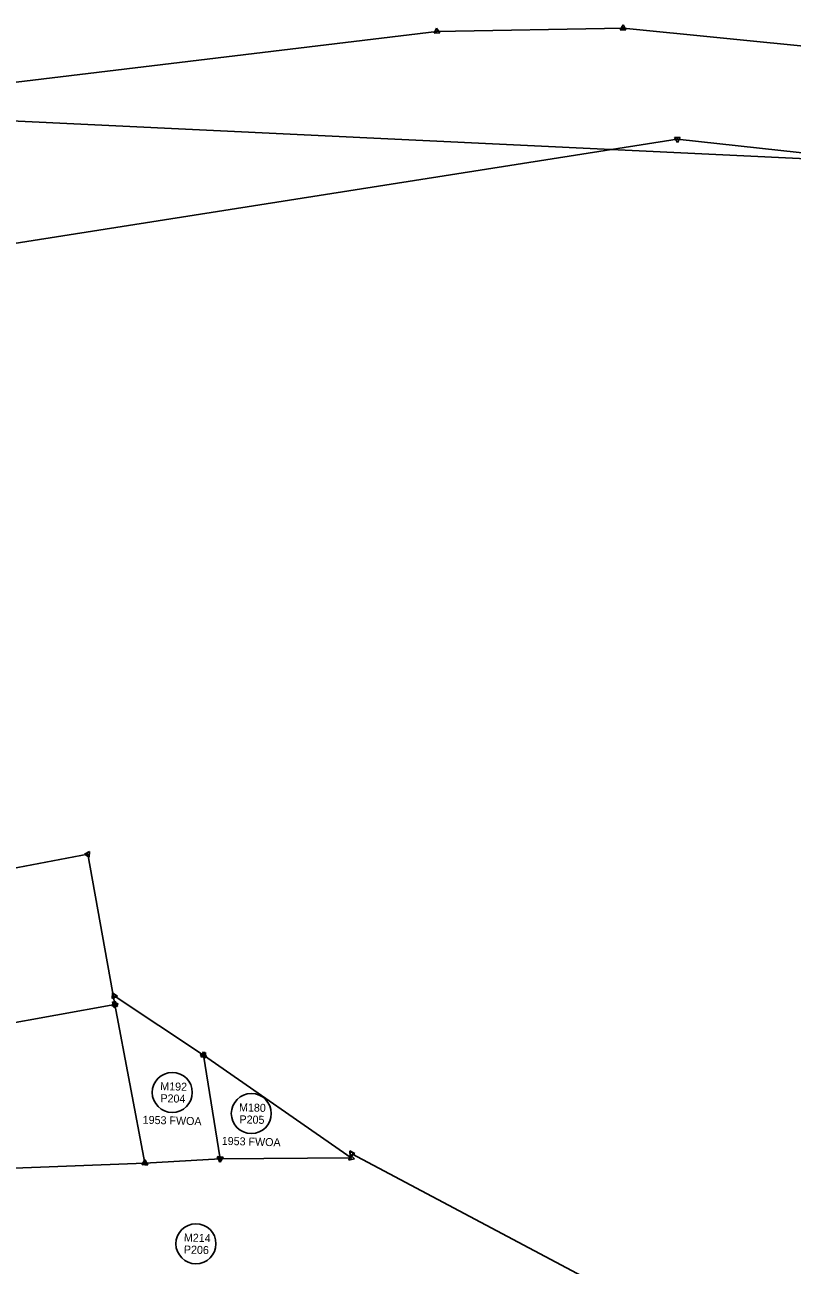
# Model space of a CAD drawing. Extents: x 325029 to 414988, y 1517527 to 1550420.
# Drawn here: x 364349 to 364852, y 1523742 to 1524556 of the extents above; entities that cross this region are included whole.
import ezdxf

# ---------------------------------------------------------------- set-up
doc = ezdxf.new("R2010")
doc.units = 0
for name, color, linetype in [('Level 56', 7, 'Continuous'), ('MEE', 7, 'Continuous'), ('MHB', 7, 'Continuous'), ('MHBWOA', 7, 'Continuous'), ('MRBL1', 7, 'Continuous')]:
    doc.layers.add(name, color=color, linetype=linetype)

msp = doc.modelspace()

# ---------------------------------------------------------------- linework, layer by layer
at = {"layer": 'Level 56'}
for centre in [(364445.48, 1523855.33), (364497.37, 1523841.48), (364461.01, 1523756.05)]:
    msp.add_circle(centre, 13.12, dxfattribs=at)
at = {"layer": 'MEE'}
msp.add_line((364824.36, 1523676.63), (364563.22, 1523815.09), dxfattribs=at)
for points in [[(364562.2, 1523813.17), (364562.06, 1523816.94)], [(364562.06, 1523816.94), (364565.4, 1523815.17)], [(364565.4, 1523815.17), (364562.2, 1523813.17)]]:
    msp.add_lwpolyline(points, dxfattribs=at)
msp.add_circle((364563.22, 1523815.09), 1.09, dxfattribs=at)
at = {"layer": 'MHB'}
for p, q in [((364095.27, 1524488.31), (364619.09, 1524551.41)), ((364619.09, 1524551.41), (364741.34, 1524553.57)), ((364741.34, 1524553.57), (364916.71, 1524536.17)), ((364776.9, 1524480.78), (364204.91, 1524390.84)), ((365204.12, 1524433.31), (364776.9, 1524480.78))]:
    msp.add_line(p, q, dxfattribs=at)
for points in [[(364617.28, 1524550.19), (364618.94, 1524553.58)], [(364621.05, 1524550.45), (364617.28, 1524550.19)], [(364618.94, 1524553.58), (364621.05, 1524550.45)], [(364739.4, 1524552.55), (364741.43, 1524555.74)], [(364743.18, 1524552.4), (364739.4, 1524552.55)], [(364741.43, 1524555.74), (364743.18, 1524552.4)], [(364774.99, 1524481.83), (364778.76, 1524481.92)], [(364776.95, 1524478.61), (364774.99, 1524481.83)], [(364778.76, 1524481.92), (364776.95, 1524478.61)]]:
    msp.add_lwpolyline(points, dxfattribs=at)
for centre in [(364619.09, 1524551.41), (364741.34, 1524553.57), (364776.9, 1524480.78)]:
    msp.add_circle(centre, 0.227, dxfattribs=at)
at = {"layer": 'MHBWOA'}
for p, q in [((364292.26, 1523993.16), (364390.03, 1524011.58)), ((364390.03, 1524011.58), (364407.8, 1523913.04)), ((364466.05, 1523879.77), (364407.31, 1523918.68)), ((364407.8, 1523913.04), (364210.73, 1523877.49)), ((364407.8, 1523913.04), (364427.48, 1523808.99)), ((364466.05, 1523879.77), (364562.91, 1523812.37)), ((364476.91, 1523811.86), (364466.05, 1523879.77)), ((364427.48, 1523808.99), (364223.73, 1523801.26)), ((364427.48, 1523808.99), (364476.91, 1523811.86)), ((364562.91, 1523812.37), (364476.91, 1523811.86))]:
    msp.add_line(p, q, dxfattribs=at)
for points in [[(364387.85, 1524011.75), (364391.26, 1524013.37)], [(364390.97, 1524009.6), (364387.85, 1524011.75)], [(364391.26, 1524013.37), (364390.97, 1524009.6)], [(364405.83, 1523912.11), (364407.98, 1523915.22)], [(364406.11, 1523916.86), (364406.34, 1523920.63)], [(364409.49, 1523918.55), (364406.11, 1523916.86)], [(364406.34, 1523920.63), (364409.49, 1523918.55)], [(364406.38, 1523914.69), (364409.94, 1523913.45)], [(364407.08, 1523910.98), (364406.38, 1523914.69)], [(364407.98, 1523915.22), (364409.59, 1523911.8)], [(364409.59, 1523911.8), (364405.83, 1523912.11)], [(364409.94, 1523913.45), (364407.08, 1523910.98)], [(364463.88, 1523879.95), (364467.3, 1523881.55)], [(364464.22, 1523878.59), (364465.95, 1523881.95)], [(364465.95, 1523881.95), (364467.99, 1523878.77)], [(364467.3, 1523881.55), (364466.98, 1523877.79)], [(364466.98, 1523877.79), (364463.88, 1523879.95)], [(364467.99, 1523878.77), (364464.22, 1523878.59)], [(364425.44, 1523808.2), (364427.8, 1523811.15)], [(364429.18, 1523807.64), (364425.44, 1523808.2)], [(364425.65, 1523807.79), (364427.35, 1523811.17)], [(364429.42, 1523808.01), (364425.65, 1523807.79)], [(364427.35, 1523811.17), (364429.42, 1523808.01)], [(364427.8, 1523811.15), (364429.18, 1523807.64)], [(364475.01, 1523812.94), (364478.79, 1523812.97)], [(364476.92, 1523809.68), (364475.01, 1523812.94)], [(364476.58, 1523809.7), (364475.21, 1523813.23)], [(364475.21, 1523813.23), (364478.95, 1523812.65)], [(364478.95, 1523812.65), (364476.58, 1523809.7)], [(364478.79, 1523812.97), (364476.92, 1523809.68)], [(364561.3, 1523810.89), (364562.42, 1523814.5)], [(364564.99, 1523811.72), (364561.3, 1523810.89)], [(364562.42, 1523814.5), (364564.99, 1523811.72)]]:
    msp.add_lwpolyline(points, dxfattribs=at)
for centre, radius in [((364390.03, 1524011.58), 0.227), ((364407.31, 1523918.68), 1.09), ((364407.8, 1523913.04), 1.09), ((364407.8, 1523913.04), 0.227), ((364466.05, 1523879.77), 1.09), ((364466.05, 1523879.77), 0.227), ((364427.48, 1523808.99), 1.09), ((364427.48, 1523808.99), 0.227), ((364476.91, 1523811.86), 1.09), ((364476.91, 1523811.86), 0.227), ((364562.91, 1523812.37), 0.227)]:
    msp.add_circle(centre, radius, dxfattribs=at)
at = {"layer": 'MRBL1'}
msp.add_line((364151.59, 1524501.69), (365471.78, 1524438.52), dxfattribs=at)

# ---------------------------------------------------------------- texts
at = {"layer": 'Level 56'}
for s, p in [('M192', (364437.55, 1523856.85)), ('P204', (364437.64, 1523848.97)), ('M180', (364489.25, 1523843.01)), ('P205', (364489.53, 1523835.12)), ('1953 FWOA', (364426.03, 1523834.82)), ('1953 FWOA', (364477.92, 1523820.97)), ('M214', (364453.08, 1523757.57)), ('P206', (364453.05, 1523749.69))]:
    msp.add_text(s, height=5.249, rotation=358.49067, dxfattribs=at).set_placement(p)

doc.saveas('drawing.dxf')
